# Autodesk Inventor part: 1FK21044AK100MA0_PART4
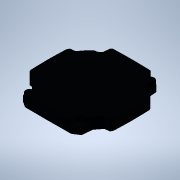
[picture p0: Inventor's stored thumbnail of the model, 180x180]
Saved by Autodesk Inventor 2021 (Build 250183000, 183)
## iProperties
Created: 2025-04
Part Number: 1FK21044AK100MA0_PART4
Material: Generic
Catalog Web Link: www.3dfindit.com
Description: -Servo synchronous motor
Document SubType Name: Modeling
Designer: psAdmin
Mass: 55.5405 g
Surface Area: 149.572 cm^2
Volume: 55.5405 cm^3
Density: 1 g/cm^3
Appearance: PSOLRGB-38-46-56
Category: PARTsolutions
Title: 1FK21044AK100MA0_PART4
Author: Cadenas PARTsolutions
Comments: Servo synchronous motor
Sending System: PARTsolutions
Preprocessor: ST-DEVELOPER v19.3
PSOL_IDENT_0: {$CADENAS_DATA/23d-libs/siemens_ag/_cat_/5e/d8/1fk21044ak100ma0.prj},213 {VTYP=3D},{NB=1FK21044AK100
PSOL_IDENT_1: MA0_PART4},{LINA=1FK21044AK100MA0_PART4},{NN=1FK21044AK100MA0_PART4},{NOPRJ=TRUE},{DATE=19.08.2025 1
PSOL_IDENT_2: 4:00:41},{GEOMDATE=30.07.2025 02:00:53},{VERSION=},{LINEID=10},{WBVAR=},{WBNUMERIC=}  {NB=1FK21044AK
PSOL_IDENT_3: 100MA0_PART4},{LINA=1FK21044AK100MA0_PART4},{KT=DUMMY},{PREVIEW=../../../_pool_/cb/72/p_d211_xx_0043
PSOL_IDENT_4: 4j.png},{DESCSHORT=SIMOTICS S-1FK2 HD, SINAMICS S210 3AC 400V-480V, 0.95 Nm, 6000 rpm},{DESCLONG=SIM
PSOL_IDENT_5: OTICS S-1FK2 HD servo motor M0=1.27 Nm; PN = 0.6 kW at nN=6000 rpm (380-480 V); PN = 0.4 kW at nN=30
PSOL_IDENT_6: 00 rpm (200-240 V); with holding brake; degree of protection IP64; cylindrical shaft D19x40mm; absol
PSOL_IDENT_7: ute encoder 22-bit + 12-bit multiturn (encoder AM22DQC); with OCC interface; plug size M17, rotatabl
PSOL_IDENT_8: e; SIMOTICS S-1FK2 servomotorfor a wide range of uses in industrial environments. SIMOTICS S‑1FK2 se
PSOL_IDENT_9: rvomotors are compact synchronous motors with a high dynamic performance that set themselves apart a
PSOL_IDENT_10: s a result of their high power density, degree of protection and overload capability. The motors are
PSOL_IDENT_11: available in two variants: as High Dynamic variant (highest dynamic performance as a result of the
PSOL_IDENT_12: low intrinsic moment of inertia for applications demanding a high dynamic performance with low moved
PSOL_IDENT_13: masses) - and as Compact variant (precise and stable closed-loop control for medium up to large mov
PSOL_IDENT_14: ed masses as a result of a medium intrinsic moment of inertia). SIMOTICSS‑1FK2 servomotors fully exp
PSOL_IDENT_15: loit their strengths in a system with the SINAMICSS210 frequency converter and simple connection usi
PSOL_IDENT_16: ng the one cable connection (OCC). Advantages include the short control and positioning times, fast
PSOL_IDENT_17: and precise correction of disturbing quantities as well as stable control with a high dynamic perfor
PSOL_IDENT_18: mance. The servo motors can be configured to address a wide range of requirements. For example with
PSOL_IDENT_19: and without holding brake, IP64 or IP65 degree of protection, singleturn or multiturn absolute encod
PSOL_IDENT_20: ers - to name just a few. Further, the servomotors are available in different shaft heights extendin
PSOL_IDENT_21: g from 20 to 100. A shaft sealing ring is available to achieve an IP65 degree of protection and for
PSOL_IDENT_22: subsequent mounting at the motor or as spare part. SIMOTICS - the optimum motor for each and every m
PSOL_IDENT_23: otion control application.},{INTNO=804766910005},{SUPPLIERALTNO=1FK2104-4AK10-0MA0},{MANUID=1FK21044
PSOL_IDENT_24: AK100MA0},{MANUNAME=Siemens},{MANUTYPEDESC=Synchronous motor 1FK2-HD 1,27 Nm},{AAU732=SIMOTICS},{AAO
PSOL_IDENT_25: 057=S-1FK2},{AAU734=SIMOTICS S-1FK2 HD servo motor M0=1.27 Nm; PN = 0.6 kW at nN=6000 rpm (380-480 V
PSOL_IDENT_26: ); PN = 0.4 kW at nN=3000 rpm (200-240 V); with holding brake; degree of protection IP64; cylindrica
PSOL_IDENT_27: l shaft D19x40mm; absolute encoder 22-bit + 12-bit multiturn (encoder AM22DQC); with OCC interface;
PSOL_IDENT_28: plug size M17, rotatable;},{AAW338=Synchronous motor 1FK2-HD 1,27 Nm},{AAO742=SIMOTICS},{AAO663=4042
PSOL_IDENT_29: 948691076},{NOCUPEROU=1},{PRICEQUANTITY=1},{QUANTITYMIN=1},{QUANTITYINT=1},{CTN=85015100},{COO=DE},{
PSOL_IDENT_30: AAO676=1FK2104-4AK10-0MA0},{AAO677=Siemens AG},{ORDERUNIT=C62},{CONTENTUNIT=C62}
NB: 1FK21044AK100MA0_PART4
NT: Servo synchronous motor
NBSYN: $MANUID._PART4
LINA: 1FK21044AK100MA0_PART4
CATALOG: SIEMENS
PREVIEW: ../../../_pool_/cb/72/p_d211_xx_00434j.png
DESCSHORT: SIMOTICS S-1FK2 HD, SINAMICS S210 3AC 400V-480V, 0.95 Nm, 6000 rpm
DESCLONG: SIMOTICS S-1FK2 HD servo motor M0=1.27 Nm; PN = 0.6 kW at nN=6000 rpm (380-480 V); PN = 0.4 kW at nN=3000 rpm (200-240 V); with holding brake; degree of protect
INTNO: 804766910005
SUPPLIERALTNO: 1FK2104-4AK10-0MA0
MANUID: 1FK21044AK100MA0
MANUNAME: Siemens
MANUTYPEDESC: Synchronous motor 1FK2-HD 1,27 Nm
AAU732: SIMOTICS
AAO057: S-1FK2
AAU734: SIMOTICS S-1FK2 HD servo motor M0=1.27 Nm; PN = 0.6 kW at nN=6000 rpm (380-480 V); PN = 0.4 kW at nN=3000 rpm (200-240 V); with holding brake; degree of protect
AAW338: Synchronous motor 1FK2-HD 1,27 Nm
AAO742: SIMOTICS
AAO663: 4042948691076.0
NOCUPEROU: 1
PRICEQUANTITY: 1
QUANTITYMIN: 1
QUANTITYINT: 1
CTN: 85015100
COO: DE
ARTICLENO: 1FK21044AK100MA0_PART4
BOMINFO: 1FK21044AK100MA0_PART4
CREATOR: CADENAS GmbH
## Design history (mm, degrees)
feature "2025_04_17_15_35_41_0874"
body "Solid1"
